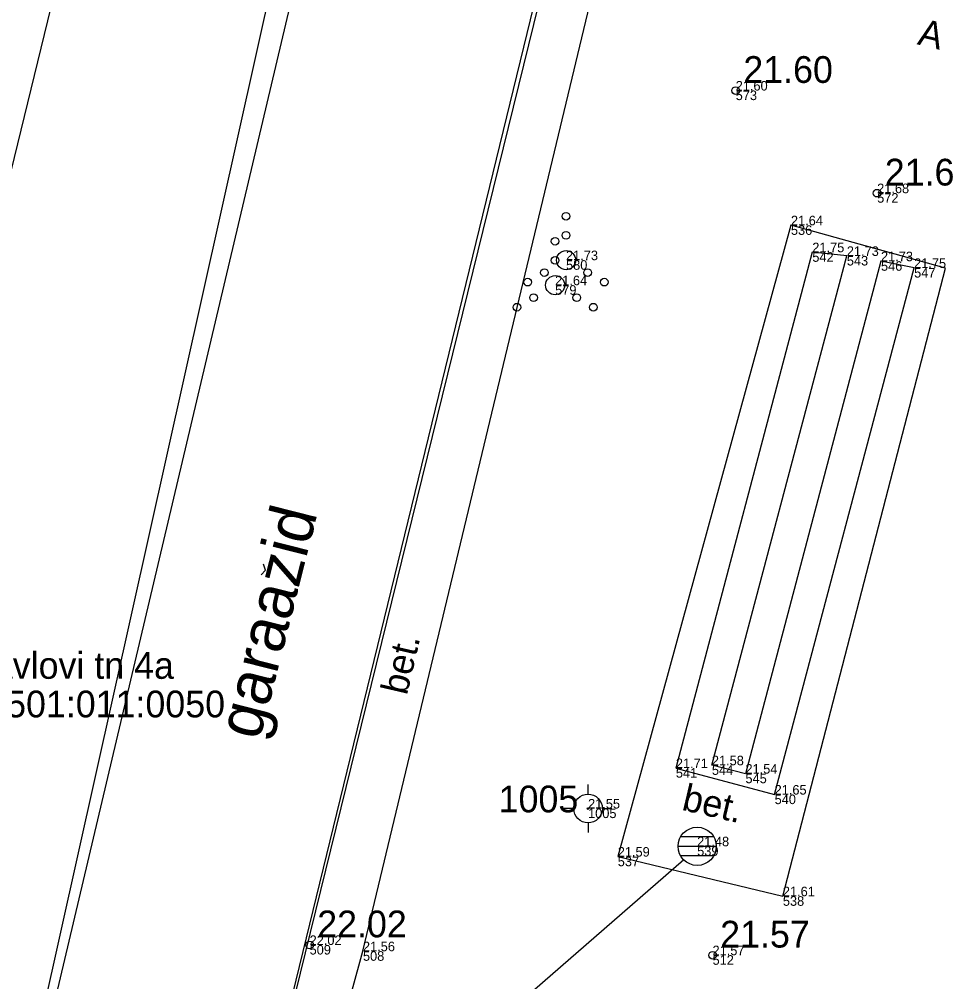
# Model space of a CAD drawing. Extents: x 714279 to 714471, y 6589851 to 6590083.
# Drawn here: x 714310.95 to 714335.18, y 6590005.81 to 6590030.99 of the extents above; entities that cross this region are included whole.
import ezdxf

# ---------------------------------------------------------------- set-up
doc = ezdxf.new("R2010")
doc.units = 0
for name, color, linetype in [('ALUSVORK', 7, 'Continuous'), ('DTRASS', 7, 'Continuous'), ('HALJASTUS', 7, 'Continuous'), ('HOONE', 7, 'Continuous'), ('KORGUS', 7, 'Continuous'), ('MOOTKORG', 7, 'Continuous'), ('MOOTMPUNKT', 7, 'Continuous'), ('MOOTPIIR', 7, 'Continuous'), ('PIIR', 7, 'Continuous'), ('RAJATIS', 7, 'Continuous'), ('SKKAEV', 7, 'Continuous'), ('TEE', 7, 'Continuous')]:
    doc.layers.add(name, color=color, linetype=linetype)

# ---------------------------------------------------------------- blocks, each defined once
blk = doc.blocks.new('RING02')
at = {"layer": 'KORGUS'}
blk.add_circle((0, 0), 0.2, dxfattribs=at)
blk = doc.blocks.new('SPYMAR')
at = {"layer": 'ALUSVORK'}
for p, q in [((0, 0.75), (0, 1.25)), ((-0.75, 0), (-1.25, 0)), ((0.75, 0), (1.25, 0)), ((0, -0.75), (0, -1.25))]:
    blk.add_line(p, q, dxfattribs=at)
for radius in [0.75, 0.044]:
    blk.add_circle((0, 0), radius, dxfattribs=at)
blk = doc.blocks.new('REKAEV')
at = {"layer": 'SKKAEV'}
for p, q in [((0.86, 0.5), (-0.86, 0.5)), ((-1, 0), (1, 0)), ((0.86, -0.5), (-0.86, -0.5))]:
    blk.add_line(p, q, dxfattribs=at)
blk.add_circle((0, 0), 1, dxfattribs=at)
blk = doc.blocks.new('VQSA')
at = {"layer": 'HALJASTUS'}
for centre, radius in [((0, 2.3), 0.2), ((0, 1.3), 0.2), ((0, 0), 0.5), ((-1.13, -0.65), 0.2), ((1.13, -0.65), 0.2), ((-2, -1.15), 0.2), ((2, -1.15), 0.2)]:
    blk.add_circle(centre, radius, dxfattribs=at)

msp = doc.modelspace()

# ---------------------------------------------------------------- linework, layer by layer
at = {"layer": 'DTRASS'}
msp.add_lwpolyline([(714328.331, 6590008.997), (714322.553, 6590003.965)], dxfattribs=at)
at = {"layer": 'HOONE'}
for points in [[(714319.159, 6590036.112), (714325.33, 6590034.654), (714314.842, 6589991.992), (714309.058, 6589993.359), (714319.159, 6590036.112)], [(714317.272, 6590016.456), (714317.393, 6590016.577), (714317.334, 6590016.737)]]:
    msp.add_lwpolyline(points, dxfattribs=at)
at = {"layer": 'MOOTPIIR'}
msp.add_lwpolyline([(714325.392, 6590064.148), (714418.405, 6590047.495), (714428.059, 6590039.059), (714392.952, 6589961.13), (714372.822, 6589966.903), (714302.696, 6589965.199), (714319.941, 6590042.637), (714325.392, 6590064.148)], dxfattribs=at)
at = {"layer": 'PIIR'}
msp.add_lwpolyline([(714331.191, 6590053.239), (714328.01, 6590040.642), (714325.217, 6590034.631), (714313.247, 6590037.362), (714302.809, 6589994.583), (714314.816, 6589992.023), (714325.215, 6590034.631)], dxfattribs=at)
at = {"layer": 'RAJATIS'}
msp.add_lwpolyline([(714334.356, 6590024.485), (714333.489, 6590024.662), (714329.944, 6590011.254), (714329.066, 6590011.473), (714332.596, 6590024.8), (714331.693, 6590024.897), (714328.124, 6590011.399), (714330.707, 6590010.707), (714334.356, 6590024.485)], dxfattribs=at)
at = {"layer": 'TEE'}
for points in [[(714308.915, 6589992.579), (714312.567, 6589991.748), (714315.741, 6589991.273), (714319.939, 6590006.608), (714326.841, 6590035.429), (714325.606, 6590035.884), (714319.931, 6590037.223), (714319.717, 6590036.149)], [(714335.175, 6590024.482), (714331.134, 6590025.601), (714326.604, 6590009.083), (714330.923, 6590008.047), (714335.175, 6590024.482)]]:
    msp.add_lwpolyline(points, dxfattribs=at)

# ---------------------------------------------------------------- block references
at = {"layer": 'ALUSVORK', "xscale": 0.5, "yscale": 0.5}
msp.add_blockref('SPYMAR', (714325.827, 6590010.342), dxfattribs=at)
at = {"layer": 'HALJASTUS', "xscale": 0.5, "yscale": 0.5}
for p in [(714325.251, 6590024.689), (714324.966, 6590024.034)]:
    msp.add_blockref('VQSA', p, dxfattribs=at)
at = {"layer": 'KORGUS', "xscale": 0.5, "yscale": 0.5}
for p in [(714329.689, 6590029.127), (714333.389, 6590026.442), (714318.543, 6590006.772), (714329.083, 6590006.504)]:
    msp.add_blockref('RING02', p, dxfattribs=at)
at = {"layer": 'SKKAEV', "xscale": 0.5, "yscale": 0.5}
msp.add_blockref('REKAEV', (714328.681, 6590009.354), dxfattribs=at)

# ---------------------------------------------------------------- texts
at = {"layer": 'ALUSVORK'}
msp.add_text('1005', height=0.7, dxfattribs=at).set_placement((714323.488, 6590010.242))
at = {"layer": 'HOONE'}
msp.add_text('garaazid', height=1.2, rotation=75.768, dxfattribs=at).set_placement((714317.24, 6590012.106))
at = {"layer": 'KORGUS'}
for s, p in [('21.60', (714329.889, 6590029.327)), ('21.68', (714333.589, 6590026.642)), ('22.02', (714318.743, 6590006.972)), ('21.57', (714329.283, 6590006.704))]:
    msp.add_text(s, height=0.7, dxfattribs=at).set_placement(p)
at = {"layer": 'MOOTKORG'}
for s, p in [('21.60', (714329.689, 6590029.127)), ('21.68', (714333.389, 6590026.442)), ('21.64', (714331.134, 6590025.601)), ('21.75', (714331.693, 6590024.897)), ('21.73', (714332.596, 6590024.8)), ('21.73', (714325.251, 6590024.689)), ('21.73', (714333.489, 6590024.662)), ('21.75', (714334.356, 6590024.485)), ('21.64', (714324.966, 6590024.034)), ('21.58', (714329.066, 6590011.473)), ('21.71', (714328.124, 6590011.399)), ('21.54', (714329.944, 6590011.254)), ('21.65', (714330.707, 6590010.707)), ('21.55', (714325.827, 6590010.342)), ('21.48', (714328.681, 6590009.354)), ('21.59', (714326.604, 6590009.083)), ('21.61', (714330.923, 6590008.047)), ('22.02', (714318.543, 6590006.772)), ('21.56', (714319.939, 6590006.608)), ('21.57', (714329.083, 6590006.504))]:
    msp.add_text(s, height=0.25, dxfattribs=at).set_placement(p)
at = {"layer": 'MOOTMPUNKT'}
for s, p in [('573', (714329.689, 6590028.877)), ('572', (714333.389, 6590026.192)), ('536', (714331.134, 6590025.351)), ('542', (714331.693, 6590024.647)), ('543', (714332.596, 6590024.55)), ('580', (714325.251, 6590024.439)), ('546', (714333.489, 6590024.412)), ('547', (714334.356, 6590024.235)), ('579', (714324.966, 6590023.784)), ('544', (714329.066, 6590011.223)), ('541', (714328.124, 6590011.149)), ('545', (714329.944, 6590011.004)), ('540', (714330.707, 6590010.457)), ('1005', (714325.827, 6590010.092)), ('539', (714328.681, 6590009.104)), ('537', (714326.604, 6590008.833)), ('538', (714330.923, 6590007.797)), ('509', (714318.543, 6590006.522)), ('508', (714319.939, 6590006.358)), ('512', (714329.083, 6590006.254))]:
    msp.add_text(s, height=0.25, dxfattribs=at).set_placement(p)
at = {"layer": 'PIIR'}
for s, p in [('I. Pavlovi tn 4a', (714308.854, 6590013.736)), ('73501:011:0050', (714309.564, 6590012.727))]:
    msp.add_text(s, height=0.7, dxfattribs=at).set_placement(p)
at = {"layer": 'TEE'}
for s, rotation, p in [('A', 346.352, (714334.418, 6590030.339)), ('bet.', 76.913, (714321.087, 6590013.287)), ('bet.', 346.8375, (714328.253, 6590010.313))]:
    msp.add_text(s, height=0.7, rotation=rotation, dxfattribs=at).set_placement(p)

doc.saveas('drawing.dxf')
